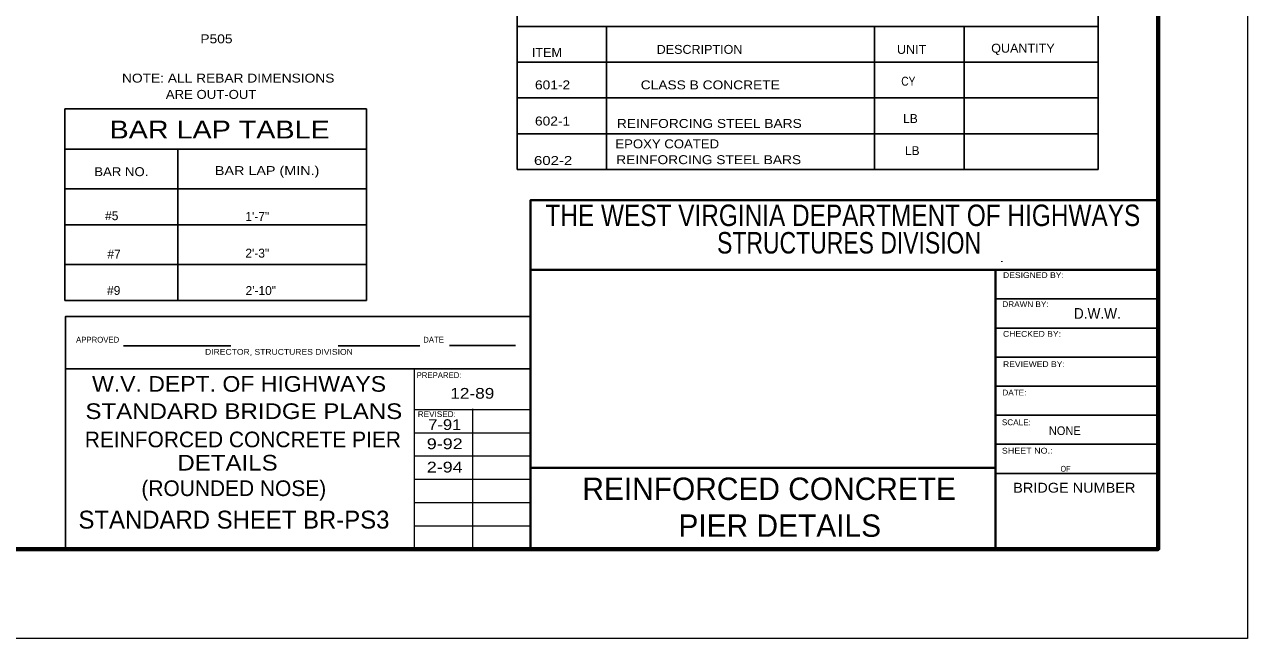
# Model space of a CAD drawing. Extents: x 14.14 to 17.34, y -1.61 to 0.38.
# Drawn here: x 16.199 to 17.339, y -1.605 to -1.033 of the extents above; entities that cross this region are included whole.
import ezdxf
from ezdxf.enums import TextEntityAlignment as Align

# ---------------------------------------------------------------- set-up
doc = ezdxf.new("R2010")
doc.units = 0
doc.header["$LTSCALE"] = 0.0033
doc.header["$PDMODE"] = 32
doc.header["$PDSIZE"] = 0.00165
doc.linetypes.add('DOTTED', pattern=[1.5, 0.3, -1.2])
doc.layers.add('1', color=7, linetype='Continuous', lineweight=40)

msp = doc.modelspace()

# ---------------------------------------------------------------- linework, layer by layer
at = {"layer": '1', "lineweight": 13}
for p, q in [((17.33925, 0.381833), (17.33925, -1.604583)), ((16.562667, -1.353417), (16.562667, -1.521417)), ((16.562667, -1.391333), (16.671, -1.391333)), ((16.616833, -1.390833), (16.616833, -1.521417)), ((16.562667, -1.413), (16.671, -1.413)), ((16.562667, -1.434667), (16.671, -1.434667)), ((16.562667, -1.456417), (16.671, -1.456417)), ((16.562667, -1.478083), (16.671, -1.478083)), ((16.562667, -1.49975), (16.671, -1.49975)), ((17.339333, -1.60475), (14.142583, -1.60475))]:
    msp.add_line(p, q, dxfattribs=at)
at = {"layer": '1', "lineweight": 25}
for p, q in [((16.658417, -1.001), (16.658417, -1.167833)), ((17.200083, -1.001), (17.200083, -1.167833)), ((16.658417, -1.0345), (17.200083, -1.0345)), ((16.74175, -1.0345), (16.74175, -1.167833)), ((16.99175, -1.0345), (16.99175, -1.167833)), ((17.075083, -1.0345), (17.075083, -1.167833)), ((16.658417, -1.067833), (17.200083, -1.067833)), ((16.658417, -1.101167), (17.200083, -1.101167)), ((16.236833, -1.289833), (16.236833, -1.11125)), ((16.236833, -1.11125), (16.51825, -1.11125)), ((16.51825, -1.11125), (16.51825, -1.289833)), ((16.658417, -1.1345), (17.200083, -1.1345)), ((16.236833, -1.149), (16.51825, -1.149)), ((16.342333, -1.289833), (16.342333, -1.149)), ((16.658417, -1.167833), (17.200083, -1.167833)), ((16.236833, -1.185917), (16.51825, -1.185917)), ((16.236833, -1.219417), (16.51825, -1.219417)), ((17.110333, -1.25375), (17.110333, -1.25325)), ((16.236833, -1.256333), (16.51825, -1.256333)), ((16.236833, -1.289833), (16.51825, -1.289833)), ((17.104333, -1.288417), (17.256, -1.288417)), ((17.104333, -1.3155), (17.256, -1.3155)), ((17.104333, -1.342583), (17.256, -1.342583)), ((16.237667, -1.353417), (16.671, -1.353417)), ((17.104333, -1.369667), (17.256, -1.369667)), ((17.104333, -1.39675), (17.256, -1.39675)), ((17.104333, -1.423833), (17.256, -1.423833)), ((17.104333, -1.451), (17.256, -1.451))]:
    msp.add_line(p, q, dxfattribs=at)
at = {"layer": '1'}
for p, q in [((16.671, -1.261333), (17.256, -1.261333)), ((17.104333, -1.261333), (17.104333, -1.521417)), ((16.671, -1.445583), (17.104333, -1.445583))]:
    msp.add_line(p, q, dxfattribs=at)
at = {"layer": '1', "linetype": 'DOTTED', "lineweight": 25}
for p, q in [((16.291583, -1.332167), (16.56775, -1.332167)), ((16.595583, -1.33175), (16.656917, -1.33175))]:
    msp.add_line(p, q, dxfattribs=at)
at = {"layer": '1', "lineweight": 70}
msp.add_line((14.309333, -1.521417), (17.256, -1.521417), dxfattribs=at)
msp.add_lwpolyline([(17.256, -1.521417), (17.256, 0.298667), (14.309333, 0.298667), (14.309333, -1.521417)], dxfattribs=at)
at = {"layer": '1'}
msp.add_lwpolyline([(14.309333, -1.521417), (16.671, -1.521417), (16.671, -1.196333), (17.256, -1.196333)], dxfattribs=at)
at = {"layer": '1', "lineweight": 25}
msp.add_lwpolyline([(16.237667, -1.521417), (16.237667, -1.304667), (16.671, -1.304667)], dxfattribs=at)
at = {"layer": '1'}
msp.add_point((17.256, -1.521417), dxfattribs=at)

# ---------------------------------------------------------------- texts
for s, height, width, p in [('P505', 0.008334, 1.15, (16.363333, -1.05025)), ('ITEM', 0.008334, 1.05, (16.672333, -1.062917)), ('DESCRIPTION', 0.008334, 1.05, (16.788583, -1.060083)), ('UNIT', 0.008334, 1.05, (17.012583, -1.060083)), ('QUANTITY', 0.008334, 1.05, (17.100417, -1.059)), ('NOTE: ALL REBAR DIMENSIONS', 0.008334, 1.15, (16.29025, -1.086833)), ('CY', 0.008334, 0.85, (17.016583, -1.08975)), ('ARE OUT-OUT', 0.008334, 1.1, (16.331083, -1.102)), ('601-2', 0.008334, 1.15, (16.675167, -1.093167)), ('CLASS B CONCRETE', 0.008334, 1.15, (16.77375, -1.093167)), ('BAR LAP TABLE', 0.01667, 1.2, (16.278667, -1.138917)), ('602-1', 0.008334, 1.15, (16.675167, -1.126833)), ('REINFORCING STEEL BARS', 0.008334, 1.15, (16.7515, -1.129083)), ('EPOXY COATED', 0.008334, 1.1, (16.750083, -1.148083)), ('602-2', 0.008334, 1.25, (16.67425, -1.163583)), ('REINFORCING STEEL BARS', 0.008334, 1.15, (16.750917, -1.162833)), ('BAR NO.', 0.008334, 1.1, (16.264417, -1.174)), ('BAR LAP (MIN.)', 0.008334, 1.2, (16.376833, -1.173)), ('DESIGNED BY:', 0.005418, 1.1, (17.111417, -1.268917)), ('DRAWN BY:', 0.005418, 1.05, (17.110833, -1.296)), ('CHECKED BY:', 0.005418, 1.1, (17.111417, -1.323667)), ('DIRECTOR, STRUCTURES DIVISION', 0.005418, 1.1, (16.367667, -1.340417)), ('REVIEWED BY:', 0.005418, 1.1, (17.111417, -1.351833)), ('W.V. DEPT. OF HIGHWAYS', 0.01458, 1.1, (16.262333, -1.374833)), ('DATE:', 0.005418, 1.05, (17.110833, -1.378333)), ('STANDARD BRIDGE PLANS', 0.01458, 1.15, (16.256167, -1.40025)), ('REVISED:', 0.005418, 1.05, (16.565917, -1.398417)), ('SCALE:', 0.005418, 1.05, (17.110333, -1.406)), ('NONE', 0.008084, 0.95, (17.154167, -1.415167)), ('  DETAILS', 0.01458, 1.15, (16.329417, -1.44825)), ('SHEET NO.:', 0.005418, 1.15, (17.110333, -1.4325)), ('OF', 0.005418, 0.9, (17.165, -1.449333))]:
    msp.add_text(s, height=height, dxfattribs=dict(at, width=width)).set_placement(p)
for s, height, p in [('LB', 0.008334, (17.018333, -1.1245)), ('LB', 0.008334, (17.02, -1.154417)), ('#5', 0.008334, (16.2745, -1.215)), ('1\'-7"', 0.008334, (16.40525, -1.215667)), ('#7', 0.008334, (16.276667, -1.250833)), ('2\'-3"', 0.008334, (16.40525, -1.249917)), ('#9', 0.008334, (16.276333, -1.284667)), ('2\'-10"', 0.008334, (16.405417, -1.28475)), ('APPROVED', 0.005417, (16.247417, -1.329083)), ('DATE', 0.005417, (16.571, -1.329083)), ('PREPARED:', 0.005418, (16.564833, -1.362083)), ('REINFORCED CONCRETE PIER', 0.01458, (16.255583, -1.426583)), ('(ROUNDED NOSE)', 0.01458, (16.308333, -1.472)), ('REINFORCED CONCRETE', 0.02083, (16.719333, -1.475667)), ('STANDARD SHEET BR-PS3', 0.01667, (16.249667, -1.502333)), ('PIER DETAILS', 0.02083, (16.808917, -1.51))]:
    msp.add_text(s, height=height, dxfattribs=at).set_placement(p)
for s, height, width, p in [('THE WEST VIRGINIA DEPARTMENT OF HIGHWAYS', 0.02, 0.85, (16.962125, -1.2205)), ('STRUCTURES DIVISION', 0.02, 0.8, (16.967917, -1.246083)), ('D.W.W.', 0.01, 0.95, (17.199333, -1.306917)), ('12-89', 0.01, 1.2, (16.61675, -1.381333)), ('7-91', 0.01, 1.15, (16.591083, -1.4105)), ('9-92', 0.01, 1.25, (16.591042, -1.428333)), ('2-94', 0.01, 1.25, (16.591042, -1.450083)), ('BRIDGE NUMBER', 0.009166, 1.1, (17.177875, -1.468833))]:
    msp.add_text(s, height=height, dxfattribs=dict(at, width=width)).set_placement(p, align=Align.CENTER)

doc.saveas('drawing.dxf')
